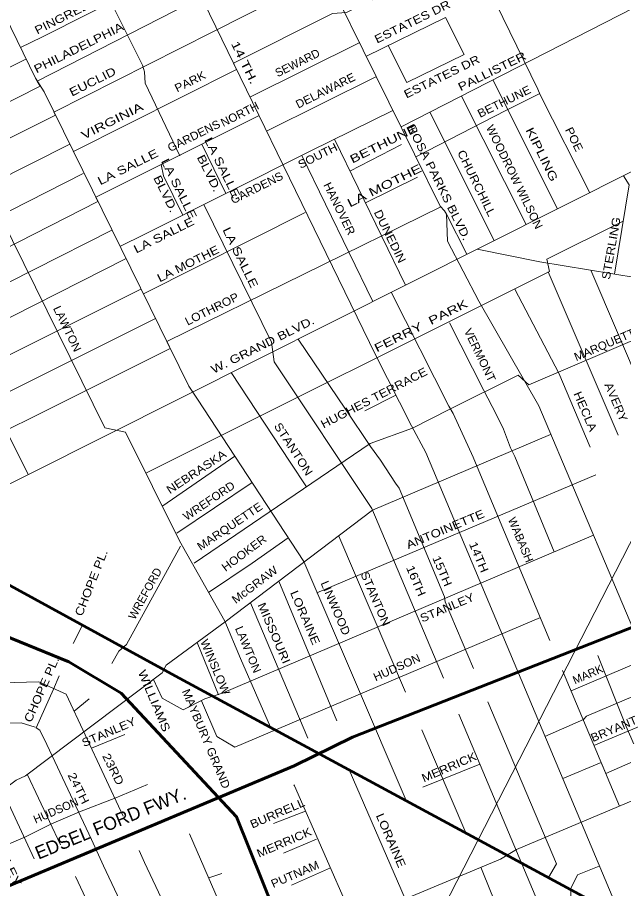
# Model space of a CAD drawing. Extents: x 34705 to 138605, y 34275 to 143551.
# Drawn here: x 84007 to 89542, y 105948 to 113900 of the extents above; entities that cross this region are included whole.
import ezdxf
from ezdxf.enums import TextEntityAlignment as Align

# ---------------------------------------------------------------- set-up
doc = ezdxf.new("R2010")
doc.units = 0
doc.header["$LTSCALE"] = 30
for name, color, linetype, lineweight in [('1', 7, 'Continuous', 13), ('11', 7, 'Continuous', 13), ('50', 7, 'Continuous', 13), ('51', 7, 'Continuous', 35)]:
    doc.layers.add(name, color=color, linetype=linetype, lineweight=lineweight)

msp = doc.modelspace()

# ---------------------------------------------------------------- linework, layer by layer
at = {"layer": '1'}
for p, q in [((85875.31, 116222.5), (87867.17, 112176.76)), ((87194.95, 113545.56), (87915.01, 113899.08)), ((87915.01, 113899.08), (88085.5, 113561.64)), ((86134.39, 113175.25), (87133.17, 113669.86)), ((87392.81, 113642.7), (87563.3, 113305.27)), ((87563.3, 113305.27), (88085.5, 113561.64)), ((86282.78, 112862.12), (87284.85, 113360.83)), ((88347.52, 113329.41), (88938.99, 112152.75)), ((88061.68, 113180.01), (88653.15, 112009.37)), ((87772.87, 113035.65), (88362.12, 111863.4)), ((86903.96, 112788.62), (87550.51, 111456.3)), ((85691.13, 112742.44), (85909.48, 112291.5)), ((87043.35, 112497.95), (87515.22, 112738.68)), ((86604.71, 112640.29), (87251.95, 111306.55)), ((87185.54, 112208.37), (87660.13, 112443.43)), ((85157.08, 111377.06), (86635.25, 112118.71)), ((87924.47, 112104.52), (88112.11, 111738)), ((88853.2, 111576.33), (89494.47, 110088.37)), ((89243.67, 111592.6), (90377.23, 108933.39)), ((87180.51, 110310.24), (87463.92, 110451.99)), ((85335.35, 109442.82), (85991.34, 109895.78)), ((86740.71, 108648.23), (89289.56, 109725.15)), ((85463.37, 109192.51), (86149.66, 109653.94)), ((86942.74, 109166.44), (87551.45, 107742.21)), ((86394.84, 108754.09), (86925.09, 107480.56)), ((86135.07, 108557.23), (86658.48, 107319.67)), ((85993.66, 107238.03), (88782.57, 108422.5)), ((84601.43, 108353.79), (84516.84, 108184.56)), ((85648.86, 108195.56), (85842.65, 107716.99)), ((89063.37, 107752.52), (89737.65, 108039.92)), ((88985.55, 107938.18), (89504.44, 106700.12)), ((85248.99, 107857.02), (85328.63, 107685.99)), ((84663.04, 107679.37), (84525.01, 107568.9)), ((85328.63, 107685.99), (85519.38, 107578.95)), ((85687.07, 107662.83), (85828.36, 107336.4)), ((88037.22, 107540.27), (90948.84, 100639.76)), ((89271.92, 107254.92), (89956.65, 107542.35)), ((84683.31, 107228.93), (84986.93, 107355.76)), ((87699.21, 107396.47), (88100.73, 106457.03)), ((85828.36, 107336.4), (85993.66, 107238.03)), ((87035.5, 107033.06), (87547.76, 105853.52)), ((87710.24, 106875.08), (88229.69, 107084.13)), ((84099.1, 106987.9), (84401.14, 106346.61)), ((86344.95, 106542.41), (86638.15, 106653.46)), ((86436.28, 106271.88), (86739.25, 106398.15)), ((85753.6, 106045), (85874.2, 106084.35)), ((86509.97, 105980.1), (86867.16, 106136.43))]:
    msp.add_line(p, q, dxfattribs=at)
for points in [[(81747.75, 122290.24), (81921.27, 121957.09), (82052.47, 121930.85), (82118.06, 121884.91), (82590.36, 120959.69), (82629.72, 120926.88), (83141.38, 119927.85), (83541.52, 119133.87), (83541.52, 119022.31), (83495.61, 118937.01), (83436.57, 118877.95), (83449.69, 118733.59), (83456.25, 118661.41), (87277.28, 110821.66), (87605.27, 110172.03), (87736.46, 109929.24), (90285.3, 103864.22), (92725.99, 98068.68)], [(81084.1, 121807.82), (81947.51, 120093.53), (82006.55, 119981.97), (82262.38, 119481.64), (82301.74, 119429.15), (82413.25, 119435.71), (82531.33, 119409.46), (82629.72, 119356.97), (82767.48, 119225.73), (82951.15, 118871.39), (83003.63, 118667.97), (82997.07, 118530.18), (82944.59, 118366.13), (82865.87, 118254.58), (82793.72, 118182.4), (84610.76, 114447.07), (84696.04, 114374.89), (85148.66, 113462.79), (85168.34, 113403.74), (85174.9, 113298.75), (85489.76, 112636)], [(80151.24, 121410.3), (81186.58, 119343.85), (81245.62, 119238.86), (81363.7, 118989.51), (81396.49, 118956.7), (82098.39, 117598.39), (84171.26, 113344.68), (84249.98, 113220.01), (85571.75, 110534.58), (85650.47, 110416.46), (86621.31, 108933.49), (87556.79, 106751.11)], [(79390.3, 120990.91), (79448.26, 120959.69), (82465.73, 114945.77), (82478.85, 114867.03), (84804.27, 110153.99), (84994.5, 110114.62), (85486.48, 109123.78), (85899.74, 108388.85), (86044.05, 108047.63), (86318.62, 107420.59)], [(80689.94, 111174.26), (84354.1, 113008.47), (84340.45, 113036.2), (85786.57, 113764.41), (86732.64, 114246.88), (86797.56, 114251.52), (89104.74, 115382.29), (89387.63, 115549.29), (91500.04, 116586.12), (91615.98, 116651.07), (94572.47, 118142.53)], [(82723.94, 109035.34), (90363.22, 112867.13), (94388.72, 114894.36), (95824.19, 115602.97)], [(80822.99, 110900.14), (80927.58, 110951.99), (84485.1, 112742.32), (84518.22, 112675.03), (86008.47, 113424.93), (85980.22, 113482.88), (86885.68, 113936.06), (87010.89, 113945.34), (89277.36, 115059.84)], [(81719.55, 114530.87), (82544.45, 112860.75), (82872.43, 112217.69), (82964.27, 112040.52), (83246.34, 111469.63), (83495.61, 110964.37), (83521.85, 110898.75), (84105.35, 109728.24)], [(84034.88, 113624.55), (84231.4, 113720.19), (85530.78, 114377.86)], [(88248.12, 114296.15), (88759.78, 113246.25), (88779.46, 113193.76), (89232.72, 112300.08)], [(80567.26, 111427.03), (84216.19, 113273.53), (84187.69, 113318.66), (85872.37, 114183.09)], [(87510.33, 112901.44), (89767.91, 114055.51), (90041.5, 114108.73), (90264.62, 114184.54)], [(80440.97, 111687.24), (81275.45, 112113.57), (81661.12, 112298.7), (84083.87, 113519.52)], [(87644.66, 112627.78), (88467.08, 113050), (88770.84, 113201.93)], [(81081.38, 110367.76), (81231.34, 110446.33), (82325.8, 110998.38), (82418.55, 111035.49), (84742.28, 112219.81), (84723.33, 112258.31), (86213.7, 113003.84)], [(84947.18, 111811.37), (85165.14, 111918.07), (86681.62, 112678.87), (87436.66, 113051.55)], [(85318.92, 112556.31), (85342.16, 112455.56), (85516.31, 112094.25)], [(80953.93, 110630.36), (81066.71, 110687.56), (82177.4, 111253.53), (82279.43, 111290.64), (84606.32, 112475.92)], [(89540.38, 112454.41), (89592.87, 112371.9), (89459.36, 111557.22)], [(82417.02, 109281.16), (82437.1, 109291.2), (82617.97, 109383.98), (82668.98, 109513.88), (85402.17, 110879.1), (85371.53, 110941.37), (87872.4, 112171.46)], [(85710.26, 112191.55), (86326.12, 110934.85), (86352.36, 110757.68), (87244.48, 109419.06), (87899.11, 107867.58)], [(87867.17, 112176.76), (87907.56, 112135.84), (87924.47, 112104.52)], [(87924.47, 112104.52), (87935.44, 111856.64), (88221.88, 111308.88), (88769.61, 110355.76), (90167.23, 107043.23), (90212.11, 106947.03), (92757.3, 100881.83), (92968.86, 100445.74), (93020.15, 100349.54), (93007.33, 100272.59), (93410.61, 99313.84), (93470.43, 99278.08), (94003.29, 98018.06), (94007.57, 97912.37), (94251.36, 97332.72)], [(85186.96, 109742.61), (88864.75, 111582.1), (88841.48, 111692.71), (89533.97, 112036.16)], [(81185.07, 110154.13), (81212.79, 110167.99), (81319.45, 110163.35), (84870.76, 111958.78)], [(88205.27, 111784.72), (88777.19, 111669.11), (91222.33, 111268.05)], [(81328.64, 109858.33), (81440.03, 109917.48), (81555.97, 109973.14), (81671.9, 110014.9), (84999.02, 111698.19)], [(81755.22, 109701.96), (81903.78, 109778.3), (81982.62, 109847.89), (85135.56, 111420.79)], [(88549.87, 111420.43), (88950.01, 110652.69), (89238.64, 109976.82)], [(87419.77, 111390.72), (87946.37, 110350.85), (87985.73, 110285.23), (88169.41, 109884.95), (88221.88, 109760.28), (88870.05, 108213.76)], [(85620.49, 108918.91), (87229.53, 110010.39), (87613.6, 110150.1), (87956.94, 110324.73), (88579.61, 110633.25), (88678.54, 110545.94), (90144.35, 111174.35)], [(82114.55, 109510.27), (82246.96, 109578.82), (82284.06, 109662.33), (85268.4, 111150.89)], [(87952.93, 111112.02), (88267.8, 110495.21), (88379.32, 110278.67), (88444.91, 110140.87), (88510.51, 109970.26), (88549.87, 109891.52), (88909.88, 109020.66)], [(86570.4, 110964.68), (87001.77, 110324.6), (87231.36, 109983.38), (87323.2, 109858.71), (87460.96, 109648.73), (87493.75, 109602.79), (87907.02, 108611.95), (87913.58, 108566.02), (88172.05, 107957.99)], [(85959.95, 110658.49), (86496.68, 109839.02), (86647.57, 109615.62)], [(70250.71, 99424.31), (70850.19, 99436.19), (73834.03, 101054.55), (75208.58, 101797.66), (76359.25, 102405.35), (76679.04, 102579.83), (78132.62, 103370.83), (78243.09, 103411.55), (82564.58, 105745.28), (82901.81, 106065.17), (82895.99, 106059.36), (83186.71, 106338.54), (83994.9, 106937.6), (84082.11, 106978.32), (85329.53, 107917.67), (85364.44, 107987.53), (85905.64, 108383.37), (87249.9, 109402.07), (88876.39, 110091.88)], [(74914.4, 104874.31), (75879.58, 104897.58), (77259.02, 104781.25), (77456.7, 104757.99), (78323.04, 104711.46), (84801.63, 104845.23), (85092.35, 104868.5), (85377.25, 104932.47), (86652.03, 105479.2), (88419.59, 106217.85), (88564.94, 106305.1), (90681.35, 107194.97), (91332.56, 107474.15), (91408.14, 107549.76), (94615.68, 108918.91), (95226.7, 109227.44), (95367, 109272.3)], [(85519.38, 107578.95), (85719.42, 107679), (85876.54, 107731.4), (89268.59, 109173.12)], [(85752.9, 108649.99), (86150.05, 108918.91), (86479.46, 109150.16)], [(85496.32, 109074.57), (85004.34, 108175.6), (84932.19, 108116.54), (84870.36, 108002.37)], [(88822.18, 107335.87), (89175.45, 107491.6), (89204.52, 107520.68), (89849.99, 107795.14), (89860.49, 107770.24), (91015.38, 108270.9)], [(83830.43, 108159.97), (83803.91, 107775.33), (83751.44, 107092.89), (84159.3, 106220.4)], [(89306.48, 108074.95), (89566.63, 107427.55), (89826.05, 106835.35)], [(83192.88, 107808.11), (84204.06, 107834.38), (84453.33, 107722.83), (84971.83, 106609.34)], [(84387.04, 107890.41), (84335.25, 107768.76), (84177.82, 107414.42), (84210.62, 107394.74), (84276.21, 107263.5), (84682.92, 106397.34), (84794.43, 106154.55), (85292.97, 105098.09), (87356, 100718.07), (87415.04, 100639.33), (87749.58, 99989.71), (87756.14, 99891.28), (88410.83, 98673.02)], [(88986.64, 106954.4), (89336.78, 107100.15), (89379.83, 106997.43), (90060.09, 107297.16), (90021.38, 107388.91), (91182.55, 107880.27)], [(88302.41, 107651.34), (88930.33, 106174.23), (88856.39, 106048.48)], [(79847.02, 107367.83), (80680.74, 107385.45), (84041.41, 107461.06), (84169.33, 107420.35)], [(83742.73, 106277.44), (84080.66, 106421.42), (84319.05, 106537.74), (84574.87, 106648.25), (84906.29, 106776.21), (84906.29, 106776.21), (85196.33, 106899.4)], [(86532.56, 106895.04), (86536.03, 106886.2), (87054.25, 105705.07), (89188.39, 100809.99)], [(85578.43, 106448.85), (86791.86, 103651.21), (86857.46, 103506.85), (87913.58, 101059.29), (87972.61, 100967.42), (88005.41, 100914.93), (88464.59, 100029.08), (88589.23, 99910.97), (88923.77, 99215.41), (89015.61, 99254.78)], [(85117.65, 106296.22), (85168.34, 106187.36), (87683.99, 100855.87), (87736.46, 100796.82), (88123.49, 100035.64), (88169.41, 99897.84), (88248.05, 99750)], [(88239.74, 106142.7), (88333.4, 105908.49), (89173.04, 103933.37), (89381.11, 103482.68)], [(89318.01, 106151.54), (89120.57, 106072.53), (89061.53, 105947.86), (89061.53, 105862.55), (89709.3, 104295.91), (89979.33, 103708.16), (90424.31, 102635.76), (90450.55, 102570.15)], [(84536.17, 106059.93), (85076.5, 104912.73), (87113.29, 100606.52), (87146.09, 100560.59), (87428.16, 100009.39), (87441.28, 99897.84), (87799.38, 99213.97)]]:
    msp.add_lwpolyline(points, dxfattribs=at)
at = {"layer": '1', "lineweight": 53}
msp.add_lwpolyline([(81141.26, 110244.39), (85447.32, 107891.61), (90110.84, 105370.56)], dxfattribs=at)
at = {"layer": '50'}
msp.add_line((76011.2, 82573.38), (90524.22, 110902), dxfattribs=at)
at = {"layer": '51', "lineweight": 60}
for points in [[(81392.26, 109727.24), (82330.6, 109176.08), (82684.09, 108829.15), (83879.08, 108261.49), (84476.11, 108016.68), (84955.05, 107731.66), (86008.84, 106604.15), (86475.71, 105436.6), (87689.56, 102647.83), (88119.74, 101652.09), (89397.64, 100005.46)], [(69855.84, 98897.31), (71068.51, 99251.13), (71798.78, 99505.57), (71908.53, 99566.11), (73894.22, 100075), (74115.76, 100095.52), (75030.66, 100259.68), (75589.64, 100438.2), (76964.04, 101123.57), (79290.25, 102354.77), (80472.84, 103069.89), (82167.24, 104949.52), (82488.27, 105229.61), (83616.5, 105873.94), (83928.31, 105972.43), (86533.5, 107068.2), (87067.87, 107328.8), (89988.97, 108477.92)]]:
    msp.add_lwpolyline(points, dxfattribs=at)

# ---------------------------------------------------------------- texts
at = {"layer": '1', "width": 1.05}
msp.add_text('NORTH', height=75, rotation=26.777, dxfattribs=at).set_placement((86054.2, 112983.5), align=Align.CENTER)
at = {"layer": '11'}
for s, rotation, width, p in [('PINGREE', 26.539, 1.2, (84430.7, 113864.39)), ('ESTATES DR', 26.201, 1.2, (87629.97, 113827.33)), ('PHILADELPHIA', 26.539, 1.25, (84583.07, 113589.9)), ('14 TH.', 296, 1.4, (86047.94, 113471.85)), ('PALLISTER', 26.199, 1.25, (88357.44, 113374.39)), ('ESTATES DR', 26.201, 1.2, (87898.68, 113325.95)), ('EUCLID', 26.654, 1.25, (84710.5, 113280.25)), ('PARK', 26.456, 1.1, (85600.35, 113281.11)), ('DELAWARE', 26.432, 1.05, (86835.84, 113198.7)), ('BETHUNE', 26.199, 1.1, (88468.25, 113098.68)), ('VIRGINIA', 26.676, 1.4, (84888.43, 112921.78)), ('GARDENS', 26.308, 1.05, (85634.7, 112785.77)), ('BETHUNE   ', 26.373, 1.4, (87419.13, 112741.06)), ('ROSA PARKS BLVD.', 296.39, 1.2, (87823.92, 112377.5)), ('WOODROW WILSON', 296, 1.05, (88512.21, 112428.15)), ('KIPLING', 296.001, 1.35, (88762.89, 112632.95)), ('POE', 295.996, 1.1, (89057.48, 112771.15)), ('LA SALLE', 296.207, 1.3, (85844.06, 112513.6)), ('LA SALLE', 26.536, 1.3, (85032.25, 112501.57)), ('SOUTH', 26.777, 1.1, (86765.31, 112603.79)), ('CHURCHILL', 296.001, 1.15, (88166.22, 112370.48)), ('LA SALLE', 296.207, 1.3, (85449.59, 112318.42)), ('BLVD.', 296.207, 1.25, (85724.26, 112461.48)), ('LA MOTHE   ', 26.583, 1.45, (87429.45, 112358.44)), ('BLVD.', 296.207, 1.25, (85326.51, 112273.7)), ('GARDENS', 26.644, 1.05, (86209.28, 112311.07)), ('HANOVER', 296.204, 1.05, (86913.93, 112137.77)), ('DUNEDIN', 296.208, 1.15, (87375.73, 111885.75)), ('LA SALLE', 26.575, 1.3, (85360.83, 111878.84)), ('STERLING', 79.985, 1.15, (89465.87, 111786.02)), ('LA SALLE', 296.004, 1.3, (86009.93, 111692.11)), ('LA MOTHE', 26.538, 1.2, (85582.05, 111618.35)), ('LOTHROP', 26.516, 1.1, (85799.26, 111205.22)), ('LAWTON', 295.824, 1.05, (84429.39, 111041.96)), ('FERRY  PARK  ', 26.643, 1.4, (87742.85, 111069.67)), ('W. GRAND BLVD.', 26.474, 1.25, (86263.26, 110877.3)), ('VERMONT', 295.712, 1.05, (88196.85, 110802.2)), ('MARQUETTE', 23.068, 1.05, (89414.31, 110891.43)), ('HUGHES TERRACE', 27.424, 1.15, (87279.92, 110394.34)), ('AVERY', 293.097, 1.1, (89439.48, 110374.85)), ('HECLA', 293.107, 1.15, (89158.59, 110289.35)), ('STANTON', 302.93, 1.15, (86496.04, 109939.48)), ('NEBRASKA', 33.576, 1.15, (85661.11, 109720.95)), ('WREFORD', 34.207, 1.05, (85776.89, 109456.39)), ('MARQUETTE', 33.994, 1.1, (85966.63, 109223.65)), ('ANTOINETTE', 22.782, 1.2, (87928.02, 109193.88)), ('HOOKER', 36.718, 1.1, (86099.07, 108981)), ('14TH', 292.717, 1.2, (88185.89, 108959.32)), ('CHOPE PL.', 68.323, 1.2, (84716.15, 108725.74)), ('15TH', 293.194, 1.2, (87851.86, 108832.76)), ('McGRAW', 37.009, 1.1, (86196.37, 108692.08)), ('16TH', 293.189, 1.2, (87612.58, 108742.87)), ('STANTON', 293.142, 1.1, (87242.72, 108578.03)), ('LINWOOD', 293.174, 1.1, (86877.61, 108494.86)), ('LORAINE', 293.299, 1.2, (86599.86, 108406.81)), ('STANLEY', 22.891, 1.15, (87945.62, 108478.62)), ('MISSOURI', 293.293, 1.2, (86316.21, 108265.3)), ('LAWTON', 292.736, 1.05, (86079.73, 108115.89)), ('WINSLOW', 292.73, 1.1, (85779.38, 107955.65)), ('HUDSON', 24.199, 1.05, (87486.53, 107932.51)), ('CHOPE PL.', 66.193, 1.2, (84262.07, 107751.68)), ('WILLIAMS', 292.73, 1.25, (85221.7, 107647.81)), ('MAYBURY GRAND', 292.73, 1.1, (85696.21, 107301.12)), ('STANLEY', 23.298, 1.15, (84856.26, 107343.07)), ('BRYANT', 22.808, 1.1, (89468.51, 107371.65)), ('MERRICK', 23.296, 1.15, (87962.66, 107022.33)), ('23RD', 296.577, 1.2, (84848.05, 107021.28)), ('24TH', 296.578, 1.25, (84531.99, 106847.26)), ('BURRELL', 23.298, 1.15, (86396.02, 106600.69)), ('LORAINE', 293.296, 1.2, (87383.39, 106373.12)), ('McKINLEY ', 295.588, 1.35, (83846.9, 106241.79)), ('MERRICK', 23.296, 1.15, (86457.14, 106334.66)), ('PUTNAM', 23.296, 1.1, (86556.58, 106044.4))]:
    msp.add_text(s, height=75, rotation=rotation, dxfattribs=dict(at, width=width)).set_placement(p, align=Align.CENTER)
for s, height, rotation, p in [('SEWARD', 75, 26.553, (86580.71, 113452.01)), ('WABASH', 75, 292.739, (88568.39, 109117.3)), ('WREFORD', 75, 61.093, (85204.9, 108622.6)), ('MARK', 75, 23.705, (89230.82, 107869.25)), ('EDSEL FORD FWY.', 120, 22.269, (84879.96, 106490.49)), ('HUDSON', 75, 23.582, (84372.58, 106626.41))]:
    msp.add_text(s, height=height, rotation=rotation, dxfattribs=at).set_placement(p, align=Align.CENTER)

doc.saveas('drawing.dxf')
